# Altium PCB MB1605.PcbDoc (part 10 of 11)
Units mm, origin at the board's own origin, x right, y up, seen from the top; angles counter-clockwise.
Board outline 100 x 79.6 mm, 6 copper layers (Top Layer, Signal Layer 1, Signal Layer 2, Signal Layer 3, Signal Layer 4, Bottom Layer), stack 1.549 mm thick; 644 components, 529 nets, 2853 pads, 1462 vias.
Unrouted connection lines stored in the file: 2.
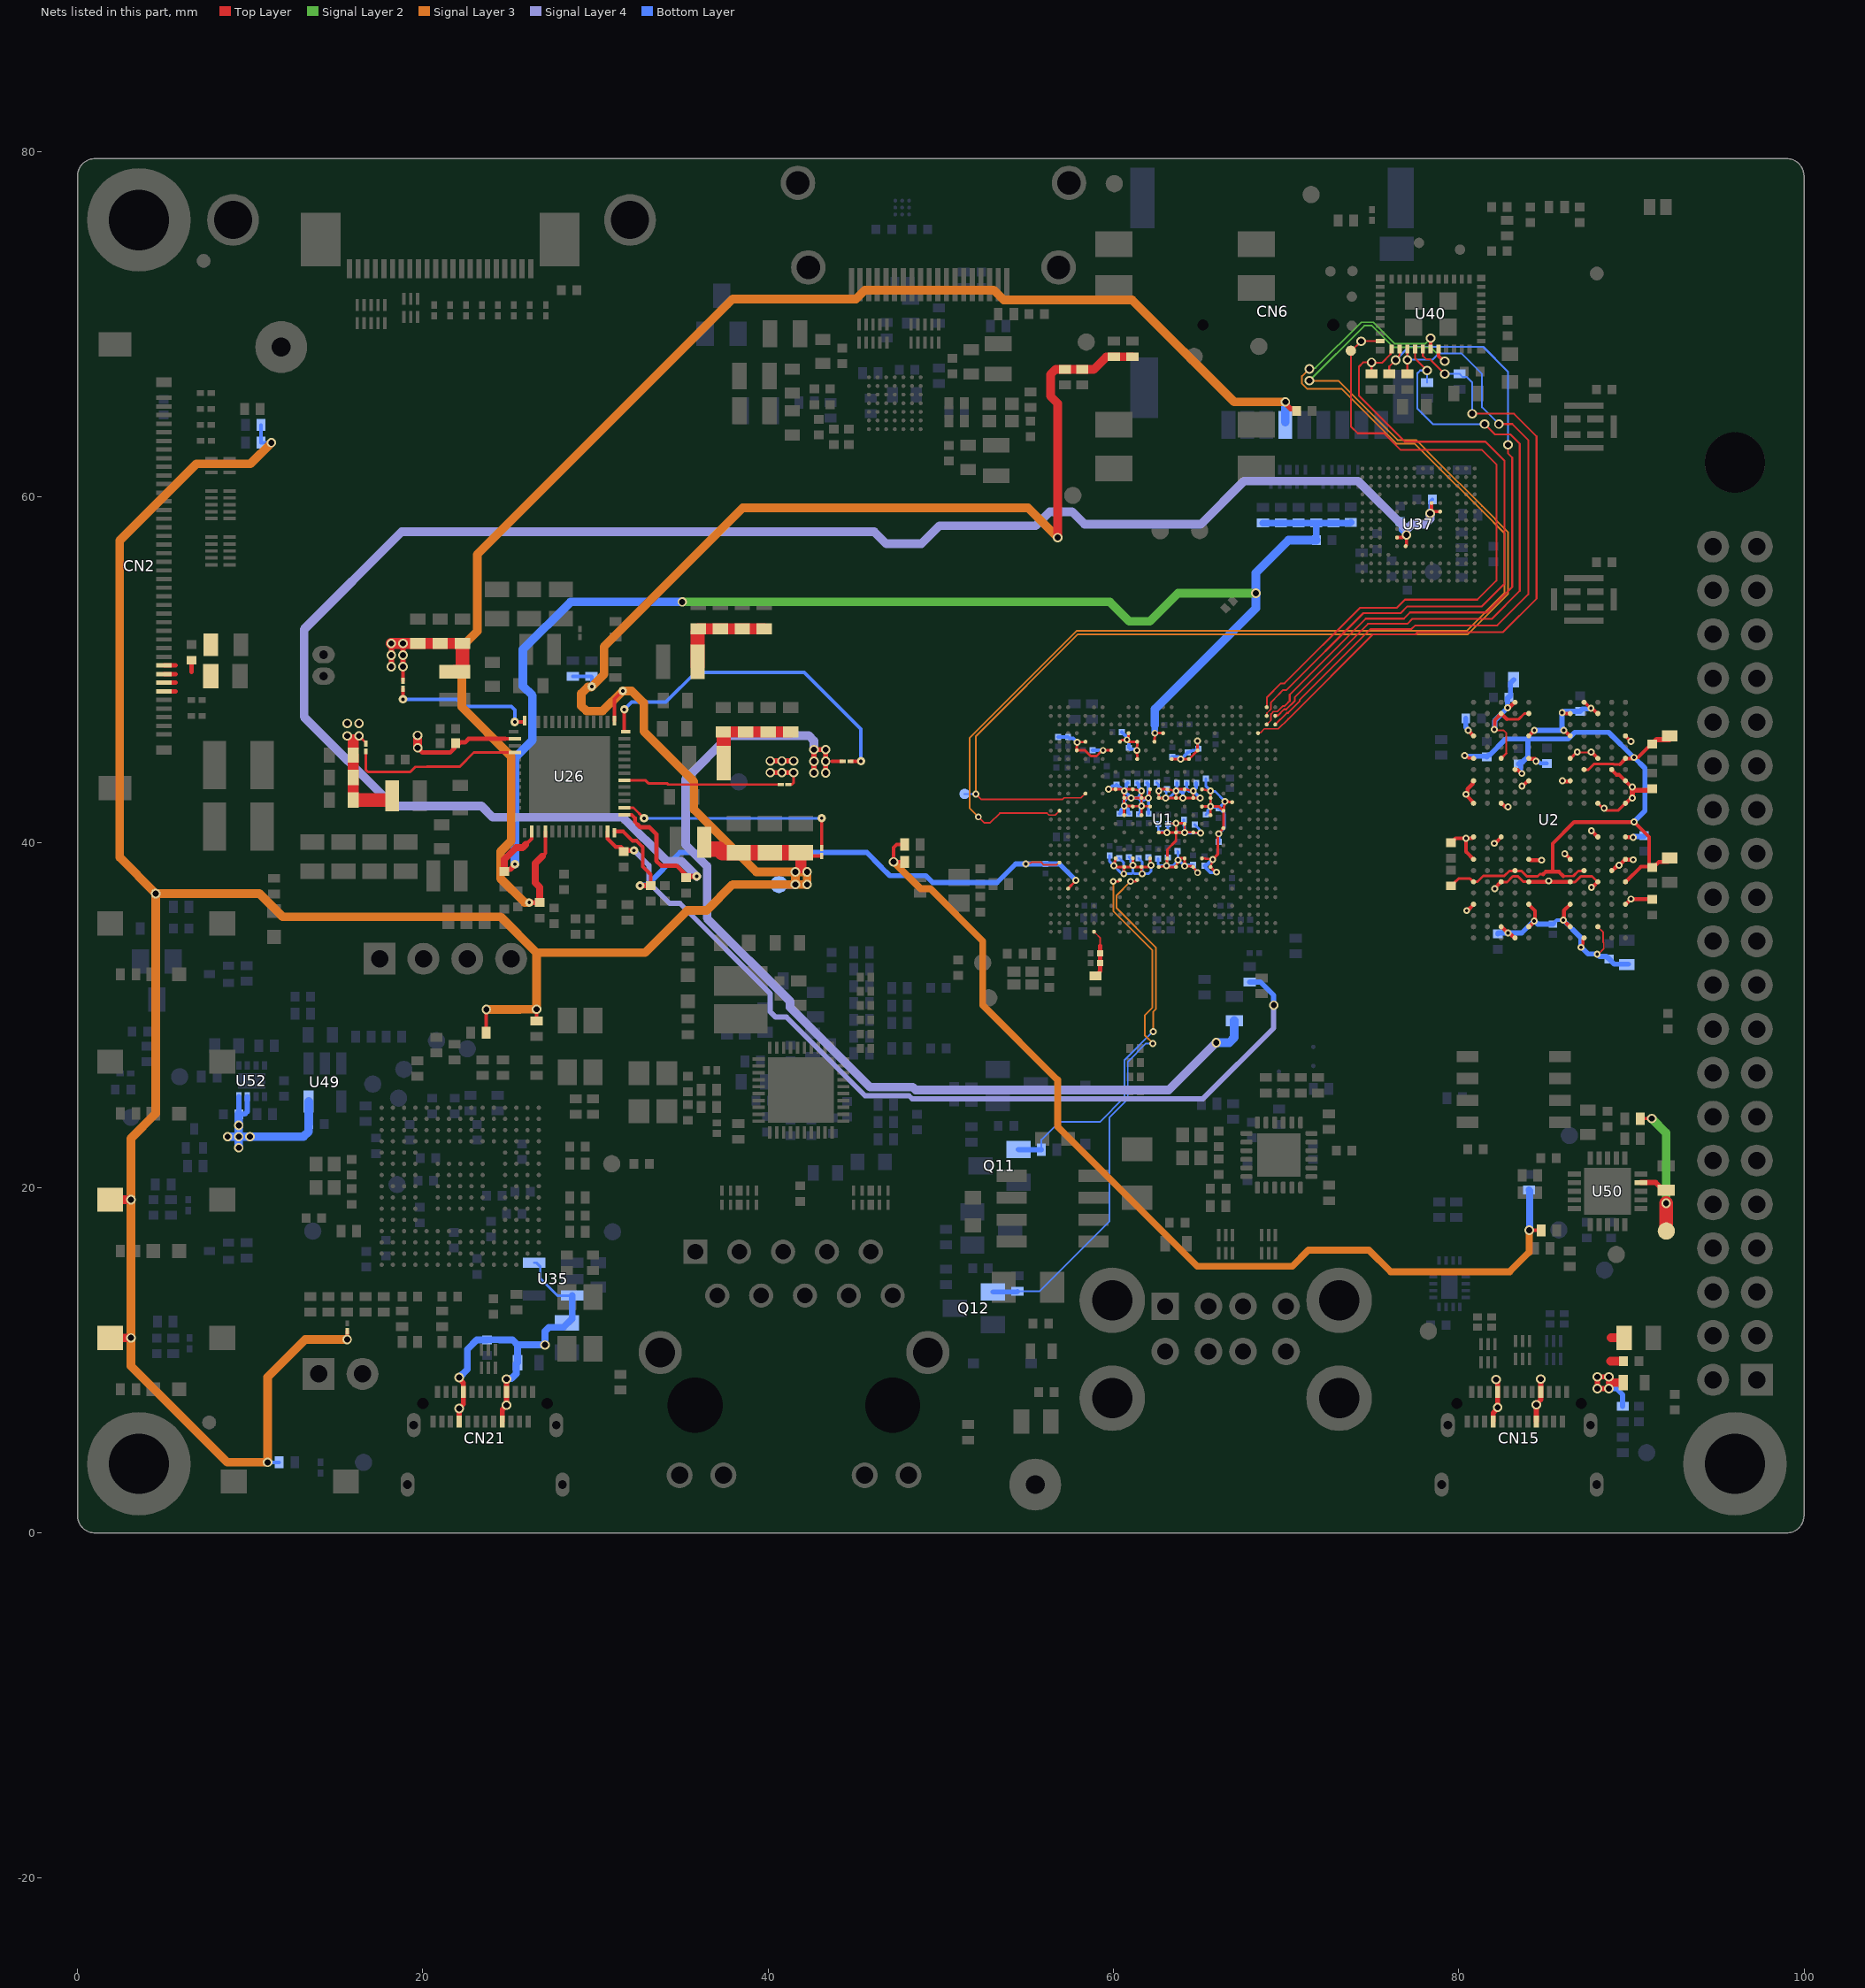
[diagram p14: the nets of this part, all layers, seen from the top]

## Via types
v1: diameter 0.55, hole 0.35, Top Layer to Bottom Layer, 823 vias
v2: diameter 0.4, hole 0.2, Top Layer to Bottom Layer, 235 vias
v3: diameter 0.4, hole 0.2, Top Layer to Bottom Layer, tented both sides, 216 vias
v4: diameter 0.5, hole 0.2, Top Layer to Bottom Layer, 159 vias
v5: diameter 0.25/0.3 (per signal layer), hole 0.1, Top Layer to Signal Layer 1, tented both sides, 29 vias

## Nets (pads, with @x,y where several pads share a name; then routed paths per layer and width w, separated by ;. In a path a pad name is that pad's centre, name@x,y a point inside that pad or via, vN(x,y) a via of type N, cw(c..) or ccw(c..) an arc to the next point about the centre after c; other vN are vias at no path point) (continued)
VBUS_STLK: C110.2 C164.1 C166.2 C172.2 CN21.A4 CN21.A9 CN21.B4 CN21.B9 U35.3 U35.5 U48.1 U49.5 U52.3 U52.4 | length 32.7
  Top Layer w0.3: CN21.B9@22.1,6.46 v1(22.1,7.213) 22.35,7.463 CN21.A4@22.35,8.16 22.35,8.682 22.1,8.932 v1(22.1,9) ; CN21.B4@24.6,6.46 24.6,7.15 v1(24.85,7.4) CN21.A9@24.85,8.16 v1(24.85,8.913)
  Bottom Layer w0.15: U35.5@26.446,15.65 26.579,15.65 26.804,15.425 26.804,14.739 27.793,13.75 U35.3@28.646,13.75
  Bottom Layer w0.3: U52.4@9.336,25.277 C172.2@9.336,24.257 9.686,24.257 9.836,24.407 U52.3@9.836,25.277
  Bottom Layer w0.4: v1(22.1,9) 22.575,9.475 22.575,10.629 23.13,11.184 23.707,11.184 C164.1@23.71,11.187 24.46,11.187 24.461,11.186 25.19,11.186 25.485,10.891 ; v1(24.85,8.913) 24.879,8.942 25.129,8.942 25.41,9.223 25.41,9.79 U48.1@25.485,9.865 25.485,10.891 ; U35.3@28.646,13.75 28.646,12.413 28.146,11.913 27.309,11.913 27.074,11.678 v1(27.074,10.891) 25.485,10.891
  Bottom Layer w0.5: v1(8.691,22.955) v1(9.336,22.955) ; v1(9.336,22.31) v1(9.336,22.955) ; C172.2@9.336,24.257 v1(9.336,23.612) v1(9.336,22.955) ; C166.2@13.39,23.667 U49.5@13.39,24.984 ; C166.2@13.39,23.691 13.385,23.686 13.385,23.248 13.093,22.955 v1(9.336,22.955)
  other v1: 9.981,22.955
VBUSc: C156.2 C159.2 CN15.A4 CN15.A9 CN15.B4 CN15.B9 R219.2 R225.1 R232.1 TP39.1 U43.1 U50.9 | length 20.2
  Top Layer w0.2: R232.1@90.513,24.003 v1(91.188,24.003)
  Top Layer w0.3: CN15.B9@82,6.46 82,6.953 82.25,7.203 v1(82.25,7.27) 82.25,8.732 82.163,8.82 v1(82.163,8.888) ; CN15.B4@84.5,6.461 84.5,6.696 84.499,6.697 84.499,7.472 84.75,7.723 v1(84.75,8.913) ; v1(88.7,8.364) v1(88.025,8.364) v1(88.025,9.039) v1(88.7,9.039) ; U50.9@90.538,20.298 91.408,20.298 91.833,19.873 R225.1@92.013,19.873
  Top Layer w0.5: 88.775,8.702 U43.1@89.525,8.702 ; 88.8,9.952 C156.2@89.55,9.952 ; 88.825,11.302 C159.2@89.575,11.302
  Top Layer w0.8: TP39.1@92.013,17.502 v1(92.013,19.098)
  Signal Layer 2 w0.5: v1(91.188,24.003) 92.013,23.178 v1(92.013,19.098)
  Bottom Layer w0.3: v1(88.7,8.364) 89.138,8.364 89.5,8.002 R219.2@89.5,7.329
  other v1: 84.499,7.422
VCONN_CC1_EN: Q11.1 R41.2 U1.AA11 | length 22.7
  Top Layer w0.15: v3(60.989,37.734) v3(60.989,37.734) 61.264,37.736 61.353,37.825 U1.AA11@61.375,37.825
  Signal Layer 3 w0.1: v3(60.989,37.734) 60.179,36.925 60.179,36.188 62.458,33.909 62.458,30.34 62.301,30.184 v2(62.301,29.041)
  Bottom Layer w0.1: R41.2@55.825,22.2 55.825,22.775 56.858,23.807 59.219,23.807 60.633,25.221 60.633,27.372 v2(62.301,29.041)
  Bottom Layer w0.3: Q11.1@54.5,22.213 54.512,22.2 R41.2@55.825,22.2
VCONN_CC2_EN: Q12.1 R200.2 U1.AA9 | length 31.1
  Top Layer w0.15: v3(59.989,37.734) v3(59.989,37.734) 60.264,37.736 60.353,37.825 U1.AA9@60.375,37.825
  Signal Layer 3 w0.1: v3(59.989,37.734) 59.989,36.015 61.929,34.075 62.258,33.746 62.258,30.423 61.825,29.99 61.825,28.808 v2(62.283,28.35)
  Bottom Layer w0.1: R200.2@54.438,13.988 55.706,13.988 59.774,18.056 59.774,24.08 60.833,25.138 60.833,27.289 61.894,28.35 v2(62.283,28.35)
  Bottom Layer w0.3: Q12.1@53.022,13.963 54.413,13.963 R200.2@54.438,13.988
VDD1_DDR: C2.2 C3.2 C4.1 C5.1 C6.1 C7.1 C8.1 C40.2 U2.F1 U2.F12 U2.G4 U2.G9 U2.T4 U2.T9 U2.U1 U2.U12 U26.44 | length 53
  Top Layer w0.15: C5.1@79.559,37.479 79.584,37.479 C5.1@79.764,37.659 ; C5.1@79.765,37.66 79.765,37.68 79.979,37.894 80.659,37.894 80.859,37.694 80.888,37.723 81.088,37.723 81.415,38.05 82.641,38.05 82.936,38.345 83.277,38.345 83.28,38.348 83.628,38.348 83.945,38.032 84.577,38.032 84.698,38.153 84.893,38.153 ; 86.059,38.044 86.632,38.044 86.925,38.337 87.252,38.337 U2.G4@87.259,38.344 ; U2.T4@87.259,44.215 87.518,44.215 87.837,44.534 88.977,44.534 88.992,44.519 89.33,44.519
  Top Layer w0.2: v2(80.34,45.025) 80.421,45.025 80.56,44.886 80.839,44.886 U2.U12@80.86,44.865
  Top Layer w0.21: 24.775,46 U26.44@25.33,46
  Top Layer w0.22: U2.T9@83.26,44.215 83.275,44.2 83.415,44.2 83.625,43.99 v2(83.659,43.99) ; 84.893,38.153 85.034,38.294 85.44,38.294 ; 86.059,38.044 85.809,38.294 85.44,38.294 ; 89.33,44.519 89.655,44.844 89.659,44.844 90,44.844 90.075,44.919 90.384,44.919 91.159,45.694 C6.1@91.184,45.694 ; U2.F1@89.65,37.683 90.561,38.594 91.179,38.594 91.034,38.739 91.034,40.316 v2(90.16,41.19) ; v2@90.146,41.176 86.685,41.176 85.44,39.931 85.44,38.294 ; C7.1@91.21,38.54 91.355,38.685 C7.1@91.411,38.685 ; C7.1@91.41,38.685 91.588,38.863 92.127,38.863 C3.2@92.183,38.919
  Top Layer w0.25: v1(19.7,46.198) v1@19.702,46.196 ; v1@19.725,45.473 v1(19.702,45.473) 19.975,45.2 21.575,45.2 21.82,45.445 21.82,45.635 21.935,45.75 C40.2@22.005,45.75 ; C40.2@22.01,45.635 22.165,45.79 22.44,45.79 22.65,46 24.775,46
  Top Layer w0.3: C6.1@91.184,45.694 C6.1@91.209,45.694 ; C6.1@91.208,45.694 91.458,45.944 C2.2@92.208,45.944
  Top Layer w0.5: v1(19.702,45.473) v1@19.702,46.196
  Bottom Layer w0.2: v2(80.34,45.025) v2@80.376,44.988 ; C4.1@81.592,44.988 C4.1@81.628,44.952
  Bottom Layer w0.22: C8.1@83.459,44.545 C8.1@83.48,44.545
  Bottom Layer w0.3: v2@80.376,44.988 C4.1@81.592,44.988 ; C4.1@81.628,44.952 81.733,45.057 81.787,45.057 82.72,45.99 84.005,45.99 84.017,45.99 ; C8.1@83.471,44.533 C8.1@83.484,44.545 ; C8.1@83.48,44.545 C8.1@83.484,44.545 ; v2@83.658,43.995 83.589,44.064 83.589,44.44 C8.1@83.484,44.545 ; v2@90.158,41.195 90.783,41.82 90.783,44.295 v2@90.158,44.92 ; v2@90.158,44.895 88.683,46.37 86.722,46.37 86.342,45.99 84.017,45.99 ; C8.1@83.484,44.545 83.589,44.65 83.693,44.65 84.017,44.974 84.017,45.99
  other v2: 90.16,44.915
VDD2_DDR: C10.2 C11.2 C12.1 C13.1 C14.1 C15.1 C16.1 C17.1 C18.1 C19.1 C20.1 C21.1 C41.2 C75.2 C76.2 C77.1 C82.2 C83.2 C200.2 C202.2 L5.2 LNK8.2 R2.2 U1.1C11 U1.1D12 U1.1E11 U1.1F12 U1.1L11 U1.1M12 U1.M22 U1.N21 U1.R21 U2.A4 U2.A9 U2.AA3 U2.AA5 U2.AA8 U2.AA10 U2.AB4 U2.AB9 U2.B3 U2.B5 U2.B8 U2.B10 U2.D1 U2.D5 U2.D8 U2.D12 U2.F3 U2.F5 U2.F8 U2.F10 U2.G2 U2.H1 U2.H5 U2.H8 U2.H12 U2.K1 U2.K3 U2.K10 U2.K12 U2.N1 U2.N3 U2.N10 U2.N12 U2.R1 U2.R5 U2.R8 U2.R12 U2.T2 U2.U3 U2.U5 U2.U8 U2.U10 U2.W1 U2.W5 U2.W8 U2.W12 | length 85.6
  Top Layer w0.09: v2@82.121,46.482 82.614,46.482 82.754,46.341 82.754,45.159 ; U2.U5@86.46,44.865 U2.U5@86.48,44.865 ; v2@86.844,45.229 v2(86.865,45.229) 86.89,45.204 87.64,45.204 v2(87.665,45.229) ; U2.AB4@87.26,48.115 U2.AB4@87.285,48.115 ; v2@87.635,47.765 v2(87.659,47.765) ; v2(88.016,33.516) 88.083,33.516 88.405,33.838 88.405,34.168 88.369,34.204 88.369,34.784 U2.B3@88.059,35.094 ; U2.K1@89.659,40.369 U2.K1@89.684,40.369
  Top Layer w0.1: U2.W8@84.06,46.165 U2.W8@84.06,46.167 ; v2@84.38,46.487 v2(84.38,46.49) ; U2.W1@89.66,46.158 U2.W1@89.66,46.165 ; v2(89.972,45.84) v2@89.972,45.846
  Top Layer w0.15: v1(16.298,46.165) 16.7,45.763 LNK8.2@16.7,45.723 ; U1.1L11@65.125,39.075 v3(65.75,39) U1.1M12@65.625,38.575 v3@65.925,38.25 ; U1.1E11@65.125,42.075 v3(65.625,42.075) ; U1.1C11@65.125,43.075 v3(65.625,42.984) U1.1D12@65.625,42.575 v3(65.625,42.075) ; U1.1F12@65.625,41.575 v3(65.625,42.075) ; U2.F10@82.459,37.694 82.469,37.704 82.803,37.704 83.129,38.03 83.389,38.03 ; U2.U10@82.46,44.865 82.754,45.159 ; 82.785,47.138 83.478,47.138 83.805,47.465 U2.AA8@84.06,47.465 ; 83.39,38.029 83.43,38.029 83.741,37.719 U2.F8@84.059,37.719 ; U2.F5@86.459,37.694 86.734,37.694 87.072,38.032 87.721,38.032 U2.F3@88.034,37.719 ; U2.U5@86.48,44.865 v2@86.844,45.229
  Top Layer w0.16: v3(65.625,42.075) 66.125,42.075 U1.N21@66.375,41.825 ; v3(65.75,39) 66.042,39.292 66.042,40.377 66.1,40.435 v3(66.1,40.5) U1.R21@66.375,40.825 U1.N21@66.375,41.825 ; U1.M22@66.875,42.325 v3(66.458,42.372) U1.N21@66.375,41.825 ; v2(87.076,33.92) 87.076,33.985 87.193,34.102 87.193,34.105 87.196,34.108 87.196,34.363 87.26,34.427 U2.A4@87.26,34.465 ; U2.N3@88.06,42.265 88.35,41.975 v2(88.425,41.975) 88.546,41.854 89.249,41.854 U2.N1@89.66,42.265
  Top Layer w0.2: v2@80.546,46.484 v2(80.546,46.49) ; U2.W12@80.86,46.165 U2.W12@80.86,46.171 ; v2(82.835,47.79) 82.873,47.828 v2@82.946,47.828 ; U2.AB9@83.233,48.115 U2.AB9@83.26,48.115 ; v2(85.99,47.505) 86.03,47.465 U2.AA5@86.46,47.465 ; U2.AB4@87.285,48.115 v2@87.635,47.765 ; v2(87.659,47.765) 87.697,47.727 87.771,47.727 88.033,47.465 U2.AA3@88.06,47.465 ; U2.W1@89.66,46.158 v2@89.972,45.846
  Top Layer w0.22: C13.1@79.559,39.979 79.814,40.235 v2(80.415,40.235) ; v2@80.488,36.045 80.51,36.045 U2.D12@80.859,36.394 ; v2@80.546,46.484 U2.W12@80.86,46.171 ; U2.H12@80.859,39.021 80.421,39.459 80.421,40.229 v2(80.415,40.235) ; U2.K12@80.859,40.294 80.856,40.297 U2.K12@80.842,40.297 ; U2.K12@80.86,40.315 U2.K12@80.842,40.297 ; U2.N12@80.86,42.265 80.86,42.301 80.414,42.747 v2(80.414,42.784) 80.414,42.832 80.504,42.922 80.504,42.924 80.51,42.93 80.51,43.093 80.82,43.403 80.82,43.503 80.86,43.543 U2.R12@80.86,43.565 ; v2@82.059,39.919 82.072,39.919 82.447,40.294 U2.K10@82.459,40.294 ; v2@82.086,37.344 82.436,37.694 U2.F10@82.459,37.694 ; v2@82.089,46.574 82.089,47.074 82.459,47.444 82.479,47.444 82.785,47.138 ; U2.B10@82.459,35.094 82.462,35.097 82.493,35.097 82.845,34.744 v2(82.86,34.744) ; U2.N10@82.459,42.244 82.491,42.244 82.497,42.25 82.672,42.074 82.826,42.074 v2@82.86,42.04 ; v2@82.859,34.719 82.893,34.685 82.997,34.685 83.237,34.444 U2.A9@83.259,34.444 ; v2@82.946,47.828 U2.AB9@83.233,48.115 ; v2(83.66,43.253) 83.704,43.253 84.016,43.565 U2.R8@84.06,43.565 ; U2.B8@84.059,35.094 v2@84.384,35.419 ; U2.D8@84.059,36.394 84.419,36.034 v2@84.419,35.503 ; U2.F8@84.059,37.719 84.072,37.707 85.122,37.706 85.134,37.719 85.147,37.706 86.447,37.706 U2.F5@86.459,37.694 ; U2.H8@84.059,39.015 84.081,39.015 84.131,38.965 v2(84.809,38.965) ; U2.U8@84.059,44.844 84.074,44.829 84.426,44.829 84.46,44.794 v2@84.509,44.794 ; U2.W8@84.06,46.167 v2@84.38,46.487 ; v2(86.01,43.565) 86.042,43.532 U2.R5@86.422,43.532 ; v2(86.085,46.49) 86.11,46.49 86.435,46.165 U2.W5@86.46,46.165 ; v2(86.145,39.34) U2.H5@86.46,39.025 ; U2.B5@86.459,35.094 86.059,35.494 86.089,35.524 86.089,36.044 U2.D5@86.46,36.415 ; v2@87.679,45.243 88.032,44.891 88.032,44.883 U2.U3@88.059,44.856 ; v2(87.685,37.39) 87.733,37.39 87.817,37.474 88.037,37.694 U2.F3@88.059,37.694 ; v2(87.685,40.665) 87.697,40.665 88.046,40.316 U2.K3@88.059,40.316 ; U2.T2@88.832,44.199 88.854,44.199 89.134,43.919 89.284,43.919 89.95,43.253 90.025,43.253 v2@90.059,43.219 ; U2.G2@88.859,38.344 88.881,38.344 v2@89.171,38.635 ; v2(89.285,38.665) 89.298,38.665 89.628,38.995 89.658,38.995 89.659,38.994 v2@90.109,38.994 ; U2.D1@89.659,36.394 89.984,36.719 C15.1@91.159,36.719 ; U2.K1@89.659,40.307 89.659,40.294 v2@90.109,40.294 ; U2.N1@89.659,42.244 89.95,42.535 90.025,42.535 v2@90.059,42.569 ; v2(80.415,40.235) 80.78,40.235 U2.K12@80.842,40.297
  Top Layer w0.3: v2@90.059,42.569 v2@90.059,43.219 ; 90.259,43.014 91.079,43.014 C14.1@91.184,43.119
  Top Layer w0.64: C202.2@15.975,42.45 C41.2@15.975,43.75 C200.2@15.975,45.05 ; 15.975,45.495 15.975,45.925
  Top Layer w0.8: C202.2@16.2,42.45 L5.2@17.975,42.45
  Bottom Layer w0.15: C82.2@65.352,41.603 65.452,41.703 65.452,41.862 65.625,42.035 v3(65.625,42.075) ; C83.2@65.363,43.698 65.363,43.246 v3(65.625,42.984) ; C75.2@66.083,41.967 66.023,42.027 65.673,42.027 v3(65.625,42.075) ; v3(66.458,42.372) 65.886,42.944 65.665,42.944 v3(65.625,42.984) ; v3(65.625,42.075) v3(65.625,42.984)
  Bottom Layer w0.16: v3(66.1,40.5) 66.44,40.84 66.44,41.65 66.218,41.872 66.178,41.872 C75.2@66.083,41.967 66.458,42.342 v3(66.458,42.372)
  Bottom Layer w0.2: C76.2@65.274,38.648 65.349,38.573 65.349,38.508 65.607,38.25 v3@65.925,38.25 ; C76.2@65.291,38.665 65.349,38.723 65.438,38.723 65.715,39 v3(65.75,39)
  Bottom Layer w0.22: C77.1@66.1,40.025 v3(66.1,40.5) ; v2@84.508,44.795 84.729,44.574 85.104,44.574 C21.1@85.108,44.57 ; R2.2@85.408,35.22 85.458,35.22 85.548,35.31 85.548,35.36 85.683,35.495 v2@86.058,35.495
  Bottom Layer w0.3: C12.1@80.409,47.185 80.409,46.676 80.546,46.539 v2(80.546,46.49) ; v2(82.06,46.54) 82.079,46.559 82.079,47.034 v2(82.835,47.79) ; C19.1@82.259,34.71 82.299,34.749 83.652,34.749 84.323,35.42 84.377,35.42 84.401,35.445 84.576,35.27 R2.2@85.459,35.27 ; v2@82.833,47.795 82.833,48.37 C16.1@82.909,48.446 ; C16.1@82.909,48.395 82.995,48.48 82.995,49.23 C10.2@83.184,49.42 ; v2(84.38,46.49) v2(86.085,46.49) 86.085,46.539 85.99,46.634 v2(85.99,47.505) 86.039,47.505 86.129,47.595 C17.1@87.034,47.595 87.169,47.731 87.625,47.731 v2(87.659,47.765) ; v2@86.059,35.495 87.076,34.478 v2(87.076,33.92) 87.103,33.92 87.488,33.536 87.997,33.536 v2(88.016,33.516) 88.087,33.46 88.161,33.402 88.552,33.402 88.579,33.35 C18.1@88.704,33.249 ; C18.1@88.603,33.35 C18.1@88.704,33.249 ; C18.1@88.709,33.245 C18.1@88.704,33.249 ; C11.2@89.833,32.945 89.008,32.945 C18.1@88.704,33.249 ; v2@90.108,40.295 90.142,40.33 90.717,40.33 C20.1@90.758,40.37
  other v1: 15.623,46.165 15.623,46.89 16.298,46.89
  other v2: 84.375,35.44 86.06,35.49 80.46,36.045 89.985,36.715 82.085,37.315 85.21,37.765 90.11,38.99 82.06,39.94 90.11,40.29 82.86,42.05 90.06,42.565 90.06,43.215 84.479,44.694
  other v3: 65.975,38.275
VDD2_DDR_FB: LNK8.1 U26.46 | length 10.2
  Top Layer w0.15: LNK8.1@16.7,45.273 16.7,44.19 16.817,44.073 19.267,44.073 19.567,44.373 20.237,44.373 20.239,44.375 22.127,44.375 22.952,45.2 U26.46@25.33,45.2
VDD3V3_USB: C61.2 R286.1 U26.13 | length 51.8
  Top Layer w0.21: U26.13@30.7,40.63 30.7,40.2 31.163,39.737 31.418,39.737 31.42,39.735 31.49,39.735 31.625,39.6 C61.2@31.625,39.53
  Top Layer w0.3: C61.2@31.625,39.53 v4(32.235,39.53)
  Signal Layer 4 w0.3: v4(32.235,39.53) 33.09,38.675 33.09,37.669 34.292,36.467 34.893,36.467 40.125,31.235 40.125,30.183 40.433,29.875 41.06,29.875 45.61,25.325 48.162,25.325 48.337,25.15 65.19,25.15 69.284,29.244 v1(69.284,30.569)
  Bottom Layer w0.3: R286.1@67.89,31.915 67.898,31.908 68.514,31.908 69.284,31.138 v1(69.284,30.569)
VDD_EMMC: C9.2 C117.2 C190.1 U26.16 U37.E6 U37.F5 U37.J10 U37.K9 | length 114.2
  Top Layer w0.2: U37.E6@76.425,57.655 76.73,57.655 76.88,57.805 v1(76.975,57.805) ; U37.F5@76.925,57.155 76.925,57.163 76.975,57.213 v1@76.975,57.655 ; v1(78.35,59.055) v1@78.425,59.13 ; U37.J10@78.425,59.655 78.425,59.225 78.417,59.217 78.417,59.138 v1@78.425,59.13 ; U37.K9@78.925,59.155 78.545,59.155 78.512,59.122 78.433,59.122 v1@78.425,59.13
  Top Layer w0.21: U26.16@31.67,41.6 32.1,41.6 32.288,41.412 32.288,41.187 32.434,41.041
  Top Layer w0.25: 32.432,41.038 32.598,40.872 33.128,40.872 33.525,40.475 33.525,38.925 33.8,38.65 34.695,38.65 35.25,38.095 C190.1@35.25,38.025
  Top Layer w0.3: C190.1@35.25,38.025 v4(35.86,38.025)
  Signal Layer 4 w0.5: v4(35.86,38.025) 34.965,38.92 34.111,38.92 31.581,41.45 24.048,41.45 23.398,42.1 18.289,42.1 13.124,47.265 13.124,52.342 18.772,57.99 46.146,57.99 46.841,57.296 48.877,57.296 49.915,58.333 55.502,58.333 56.307,59.139 57.609,59.139 58.324,58.425 65.064,58.425 67.565,60.926 74.175,60.926 76.985,58.117 77.293,58.425 78.032,58.425 78.34,58.733 78.34,59.045 v1(78.35,59.055)
  Bottom Layer w0.2: C9.2@76.615,58.58 76.615,58.074 76.884,57.805 v1(76.975,57.805) ; v1(78.35,59.055) 78.35,59.739 C117.2@78.475,59.864
VDD_SDCARD: C215.1 C218.2 CN6.4 U26.4 | length 85.8
  Top Layer w0.21: 26.925,39.2 27.1,39.375 U26.4@27.1,40.63
  Top Layer w0.3: v4(26.165,36.51) C215.1@26.775,36.51 ; v1(69.96,65.511) 70.008,65.463 70.008,65.373 70.261,65.12 70.505,65.12 70.61,65.015 C218.2@70.61,64.99
  Top Layer w0.4: C215.1@26.775,36.51 26.775,37.393 26.51,37.658 26.51,38.785 26.925,39.2
  Signal Layer 3 w0.5: v4(26.165,36.51) 25.89,36.51 24.5,37.9 24.5,39.467 25.115,40.083 25.115,44.981 22.253,47.843 22.253,51.327 23.158,52.232 23.158,56.674 37.95,71.466 45.091,71.466 45.605,71.98 53.072,71.98 53.639,71.413 61.083,71.413 66.984,65.511 v1(69.96,65.511)
  Bottom Layer w0.5: CN6.4@69.96,64.35 v1(69.96,65.511)
VDDA1V8_AON: C189.2 C234.2 U1.AB3 U1.W2 U26.14 | length 35.4
  Top Layer w0.09: 56.026,38.692 56.705,38.692 56.837,38.825 U1.W2@56.875,38.825 ; v3@57.825,37.775 v3(57.825,37.8)
  Top Layer w0.1: v2(54.932,38.744) 54.99,38.801 55.205,38.801 55.267,38.863 55.805,38.863 55.975,38.692 56.026,38.692
  Top Layer w0.15: U1.AB3@57.375,37.325 v3@57.825,37.775
  Top Layer w0.21: U26.14@31.1,40.63 31.61,40.63 32.148,40.092 32.387,40.092 32.745,39.734 32.745,38.602 33.2,38.147 C189.2@33.2,37.49
  Top Layer w0.3: v4(32.59,37.49) C189.2@33.2,37.49
  Bottom Layer w0.3: v4(32.59,37.49) 32.628,37.528 33.005,37.528 34.887,39.41 45.714,39.41 46.542,38.582 46.542,38.57 47.042,38.07 49.132,38.07 49.531,37.67 53.261,37.67 54.334,38.744 v2(54.932,38.744) 54.936,38.748 C234.2@56.064,38.748 56.877,38.748 v3(57.825,37.8)
VDDCORE: C22.2 C23.2 C24.2 C44.1 C45.2 C46.2 C47.1 C48.2 C49.2 C50.2 C51.2 C183.2 C192.2 C197.2 C201.2 L2.2 LNK2.2 R11.1 U1.1C1 U1.1C3 U1.1C5 U1.1D2 U1.1D4 U1.1E3 U1.1E5 U1.1F2 U1.1F4 U1.E5 U1.F4 U1.F8 | length 86.8
  Top Layer w0.15: U1.E5@58.375,45.825 v3(57.9,45.8) U1.F4@57.875,45.325 58.365,45.325 58.685,45.005 59.019,45.005 59.339,45.325 v3(59.4,45.325) U1.F8@59.875,45.325 ; v3(59.725,43.075) U1.1C1@60.125,43.075 60.534,43.075 v3(60.625,42.983) ; U1.1F2@60.625,41.575 v3(60.625,42.1) ; U1.1F4@61.625,41.575 v3(61.625,42.1) ; U1.1E5@62.125,42.075 v3(61.625,42.1) ; U1.1C5@62.125,43.075 v3(62.017,42.572) U1.1D4@61.625,42.575 ; v3(60.625,42.1) U1.1D2@60.625,42.575 ; v3(60.625,42.1) 61.1,42.1 U1.1E3@61.125,42.075 v3(61.625,42.1) ; U1.1D2@60.625,42.575 v3(60.625,42.983) ; U1.1D2@60.625,42.575 v3(61.017,42.572) 61.622,42.572 U1.1D4@61.625,42.575 ; v3(60.625,42.983) 60.717,43.075 U1.1C3@61.125,43.075 v3(61.625,42.983) U1.1D4@61.625,42.575 ; v3(61.625,42.1) U1.1D4@61.625,42.575
  Top Layer w0.2: C22.2@39.775,52.375 C22.2@39.823,52.423 ; 43.7,44.7 LNK2.2@44.316,44.7
  Top Layer w0.3: v1(42.656,44.024) v1(42.656,44.699) v1(42.656,45.374) v1(43.331,45.374) v1(43.331,44.699) v1(43.331,44.024)
  Top Layer w0.64: C183.2@35.95,52.375 C24.2@37.225,52.375 C23.2@38.5,52.375 C22.2@39.775,52.375
  Top Layer w0.8: L2.2@35.915,50.2 L2.2@35.915,50.45 C183.2@35.915,52.173
  Signal Layer 4 w0.5: v1(42.656,45.374) 42.656,45.88 42.363,46.173 37.744,46.173 35.227,43.656 35.227,39.858 36.46,38.625 36.46,35.607 41.275,30.792 41.275,30.441 45.891,25.825 48.37,25.825 48.545,25.65 63.206,25.65 v1@65.947,28.391
  Bottom Layer w0.2: C192.2@56.8,46.1 C201.2@57.375,46.1 57.45,46.025 57.675,46.025 v3(57.9,45.8) ; C197.2@58.788,45.342 59.383,45.342 v3(59.4,45.325) ; v3(59.725,43.075) 59.747,43.075 59.942,43.27 60.098,43.27 C45.2@60.173,43.345 v3(60.625,42.983) ; C44.1@60.351,41.659 60.355,41.659 60.426,41.73 60.426,41.883 60.625,42.082 v3(60.625,42.1) ; C51.2@60.814,43.438 60.739,43.363 60.739,43.151 60.625,43.038 v3(60.625,42.983) ; C46.2@60.915,41.655 60.84,41.73 60.84,41.94 60.719,42.062 60.663,42.062 v3(60.625,42.1) ; C49.2@61.377,43.437 61.452,43.362 61.452,43.201 61.625,43.028 v3(61.625,42.983) 61.455,42.572 ; C47.1@61.476,41.631 61.551,41.706 61.551,41.972 61.625,42.046 v3(61.625,42.1) 61.623,42.102 61.623,42.405 ; C50.2@61.941,43.438 62.017,43.362 v3(62.017,42.572) ; C48.2@62.038,41.657 62.038,42.551 v3(62.017,42.572) ; v3(60.625,42.1) 60.625,42.423 60.774,42.572 v3(61.017,42.572) ; v3(60.625,42.983) 61.017,42.591 v3(61.017,42.572) ; v3(61.017,42.572) 61.455,42.572 ; 61.455,42.572 61.623,42.405 ; 61.623,42.405 v3(62.017,42.572)
  Bottom Layer w0.5: v1@65.97,28.4 66.707,28.4 67,28.693 R11.1@67,29.675
  other v1: 65.956,28.4
VDDCORE_FB: LNK2.1 U26.28 | length 19.7
  Top Layer w0.2: U26.28@31.67,46.4 v4(31.67,47.7) ; LNK2.1@44.766,44.7 v4(45.376,44.7)
  Bottom Layer w0.2: v4(31.67,47.7) 32.097,48.127 34.077,48.127 35.8,49.85 42.087,49.85 45.376,46.561 v4(45.376,44.7)
VDDCPU: C26.2 C27.2 C28.2 C62.1 C63.2 C64.2 C65.1 C66.2 C67.2 C68.2 C69.2 L3.2 LNK4.1 U1.1C7 U1.1C9 U1.1D6 U1.1D8 U1.1D10 U1.F18 U1.G15 U1.G17 | length 26.3
  Top Layer w0.15: U1.G15@63.375,44.825 v3(63.9,44.825) U1.G17@64.375,44.825 U1.F18@64.875,45.325 v3(64.875,45.875) ; v3(65.017,42.572) U1.1D10@64.625,42.575 ; U1.1D8@63.625,42.575 63.02,42.575 v3(63.017,42.572) U1.1D6@62.625,42.575 v3(62.625,42.983) 62.716,43.075 U1.1C7@63.125,43.075 v3(63.625,42.983) ; U1.1D8@63.625,42.575 v3(63.625,42.983) ; U1.1D8@63.625,42.575 v3(64.017,42.572) 64.622,42.572 U1.1D10@64.625,42.575 ; v3(63.625,42.983) 63.716,43.075 U1.1C9@64.125,43.075 v3(64.625,42.983) U1.1D10@64.625,42.575
  Top Layer w0.2: LNK4.1@18.85,49.35 v1(18.85,50.173)
  Top Layer w0.3: v1(18.175,50.173) v1(18.175,50.848) v1(18.175,51.523) v1(18.85,51.523) v1(18.85,50.848) v1(18.85,50.173)
  Top Layer w0.64: v1(18.175,51.523) v1(18.175,51.523) C27.2@19.7,51.525 C28.2@21,51.525 C26.2@22.3,51.525
  Top Layer w0.8: L3.2@21.85,49.875 22.3,49.875 22.3,51.173
  Bottom Layer w0.15: C63.2@62.506,43.455 62.606,43.355 62.606,43.269 62.608,43.267 62.608,43.001 v3(62.625,42.983) 62.625,42.684 62.737,42.572 v3(63.017,42.572) v3@63.062,42.617 ; C62.1@63.106,43.078 63.062,43.034 v3@63.062,42.617 ; v3(63.625,42.983) 63.261,42.62 63.065,42.62 v3@63.062,42.617 ; v3(64.875,45.875) 64.895,45.855 C66.2@64.895,45.441
  Bottom Layer w0.2: C67.2@63.4,44.95 63.775,44.95 v3(63.9,44.825) 63.933,44.825 64.23,45.122 64.23,45.127 64.3,45.197 C69.2@64.305,45.197 ; C65.1@63.675,43.434 63.675,43.033 v3(63.625,42.983) 64.017,42.903 ; v3(64.017,42.572) 64.017,42.903 ; C68.2@64.239,43.447 64.239,43.125 ; C69.2@64.305,45.202 64.579,45.324 64.778,45.324 C66.2@64.886,45.432 ; v3@64.625,42.964 v3(64.625,42.983) ; C64.2@64.8,43.446 64.8,43.158 v3(64.625,42.983) ; C66.2@64.853,45.445 C66.2@64.886,45.432 ; C66.2@64.895,45.441 C66.2@64.886,45.432 ; C66.2@64.915,45.421 C66.2@64.886,45.432 ; v3(65.017,42.572) v3(64.625,42.983) ; 64.017,42.903 64.239,43.125 ; 64.239,43.125 64.381,42.983 v3(64.625,42.983)
VDDCPU_FB: LNK4.2 U26.42 | length 8.6
  Top Layer w0.2: v4(18.85,48.29) LNK4.2@18.85,48.9 ; v4(25.325,46.975) U26.42@25.895,46.975
  Bottom Layer w0.2: v4(18.85,48.29) 21.979,48.29 22.394,47.875 25.123,47.875 25.325,47.673 v4(25.325,46.975)
VDDGPU: C34.2 C35.2 C36.2 C37.2 C52.2 C53.2 C54.2 C55.2 C57.2 C58.2 C59.2 C60.2 L4.2 LNK7.2 U1.1G7 U1.1G9 U1.1H6 U1.1H8 U1.1H10 U1.1L7 U1.1L9 U1.1M6 U1.1M8 U1.1M10 | length 28.4
  Top Layer w0.1: U1.1H6@62.625,40.575 U1.1H6@62.625,40.61
  Top Layer w0.125: U1.1G9@64.125,41.075 v3(64.125,40.575) U1.1H10@64.625,40.575
  Top Layer w0.15: LNK7.2@41.175,43.35 41.182,43.358 41.385,43.358 41.473,43.445 v1(41.473,44.038) ; U1.1M6@62.625,38.575 v3(63.075,38.65) ; U1.1H6@62.625,40.575 v3(63.1,40.575) U1.1H8@63.625,40.575 ; U1.1G7@63.125,41.075 v3(63.625,41.1) ; v3(64.125,40.575) U1.1H8@63.625,40.575 ; U1.1G9@64.125,41.075 64.1,41.1 v3(63.625,41.1) ; v3(64.876,38.245) U1.1M10@64.625,38.575 64.571,38.629 v3(64.125,38.629) U1.1L9@64.125,39.075 63.851,39.075 v3(63.747,38.971) U1.1M8@63.625,38.575 63.15,38.575 v3(63.075,38.65) ; v3(63.075,38.65) U1.1L7@63.125,39.075 63.125,39.59 63.625,40.09 U1.1H8@63.625,40.575 ; U1.1H8@63.625,40.575 v3(63.625,41.1)
  Top Layer w0.16: U1.1H10@64.625,40.575 v3(65.05,40.55)
  Top Layer w0.2: C35.2@41.55,46.393 C35.2@41.598,46.345
  Top Layer w0.3: v1(40.123,44.038) v1(40.798,44.038) v1(41.473,44.038) ; v1(40.123,44.713) v1(40.798,44.713) v1(41.473,44.713)
  Top Layer w0.64: C37.2@37.4,46.4 C36.2@38.7,46.4 C34.2@40,46.4 C35.2@41.3,46.4
  Top Layer w0.8: L4.2@37.425,44.6 37.425,46.073
  Bottom Layer w0.15: C57.2@62.592,39.053 62.592,38.738 62.68,38.65 v3(63.075,38.65) ; C55.2@62.6,41.05 62.6,40.711 62.688,40.623 63.052,40.623 v3(63.1,40.575) 63.162,40.637 C52.2@63.162,41.057 63.184,41.079 63.603,41.079 v3(63.625,41.1) 63.625,40.719 63.769,40.575 v3(64.125,40.575) ; C60.2@63.154,39.122 63.092,39.06 63.092,38.667 v3(63.075,38.65) ; C59.2@63.714,39.486 63.747,39.453 v3(63.747,38.971) ; C53.2@64.083,41.306 64.083,40.962 64.125,40.919 v3(64.125,40.575) ; C54.2@64.706,41.029 65.002,40.733 65.002,40.598 v3(65.05,40.55) 64.15,40.55 v3(64.125,40.575) ; v3(64.876,38.245) 64.876,38.289 64.707,38.458 64.707,38.597 C58.2@64.607,38.697 64.193,38.697 v3(64.125,38.629) 63.783,38.971 v3(63.747,38.971) ; v3(63.075,38.65) 63.426,38.65 v3(63.747,38.971)
VDDGPU_FB: LNK7.1 U26.21 | length 9.3
  Top Layer w0.15: U26.21@31.55,43.6 32.883,43.6 33.06,43.423 34.14,43.423 34.213,43.35 LNK7.1@40.725,43.35
VDDIO: B4.1 B5.1 C70.1 C71.2 C72.2 C73.1 C74.2 C185.2 C186.2 C187.2 C196.2 C205.2 L6.2 LNK11.2 LNK13.1 R27.2 R31.2 R32.2 R33.2 R44.2 R67.2 R107.2 R122.2 R123.2 R124.2 R125.2 R223.2 R245.2 R246.2 R260.2 R261.2 TP2.1 TP4.1 U1.1L1 U1.1L3 U1.1L5 U1.1M2 U1.1M4 U1.D10 U1.E9 U1.E11 U1.G11 U26.29 | length 294.2
  Top Layer w0.15: U1.1L1@60.125,39.075 v3(60.025,38.65) 60.1,38.575 U1.1M2@60.625,38.575 ; U1.E9@60.375,45.825 60.397,45.825 60.488,45.916 60.756,45.916 v3(60.78,45.94) 60.895,45.825 U1.E11@61.375,45.825 v3(61.35,45.325) U1.G11@61.375,44.825 ; v3(60.6,38.175) U1.1M2@60.625,38.575 ; v3@60.866,46.094 60.866,46.316 U1.D10@60.875,46.325 ; U1.1L3@61.125,39.075 v3(61.125,38.675) ; v3(61.663,38.175) 61.625,38.212 U1.1M4@61.625,38.575 ; U1.1L5@62.125,39.075 62.125,38.793 62.175,38.743 v3(62.175,38.675) 62.075,38.575 U1.1M4@61.625,38.575 ; U1.1M2@60.625,38.575 61.025,38.575 v3(61.125,38.675) ; v3(61.125,38.675) 61.225,38.575 U1.1M4@61.625,38.575
  Top Layer w0.2: v1(15.615,11.207) LNK13.1@15.615,11.687 ; R107.2@23.675,28.982 23.675,30.322 v1(23.677,30.325) ; R125.2@26.59,29.657 v1(26.59,30.332) ; U26.29@31.1,47.045 31.1,48.298 v4(31.575,48.773) ; C186.2@41.9,39.4 42.085,39.215 LNK11.2@43.1,39.215 ; v1(47.267,38.87) 47.267,39.699 47.441,39.873 R245.2@47.905,39.873 ; v1@47.269,38.872 R27.2@47.905,38.872 ; v1(84.08,17.535) R223.2@84.755,17.535
  Top Layer w0.5: B5.1@1.886,11.3 v1(3.095,11.3) ; B4.1@1.886,19.3 v1(3.095,19.3) ; v1(56.775,57.65) 56.775,65.427 56.359,65.843 56.359,67.102 56.652,67.395 57.195,67.395 R44.2@57.2,67.4 R122.2@58.2,67.4 58.201,67.401 58.864,67.401 59.583,68.12 60.02,68.12 R124.2@60.025,68.125 R123.2@61.1,68.125
  Top Layer w0.64: 41.9,38.525 C186.2@41.9,38.955
  Top Layer w0.9: L6.2@36.35,39.6 37.15,39.6 37.35,39.4 C187.2@38.3,39.4 C185.2@40.1,39.4 C186.2@41.9,39.4
  Signal Layer 3 w0.4: v1(47.267,38.87) 48.827,37.31 49.399,37.31 52.431,34.278 52.431,30.573 56.764,26.24 56.764,23.546 64.86,15.45 70.36,15.45 71.294,16.384 74.797,16.384 76.051,15.13 82.951,15.13 84.08,16.259 v1(84.08,17.535)
  Signal Layer 3 w0.5: v1(11.231,63.15) 10.006,61.925 6.875,61.925 2.442,57.492 2.442,39.126 v1(4.532,37.035) ; v1(15.615,11.207) 13.193,11.207 11.011,9.025 v1(11.011,4.09) 8.667,4.09 3.095,9.662 v1(3.095,11.3) v1(3.095,19.3) 3.095,22.849 4.532,24.286 v1(4.532,37.035) ; v1(23.677,30.325) 23.701,30.325 25.627,30.325 25.634,30.332 v1(26.59,30.332) 26.59,33.61 ; v1(56.775,57.65) 55.053,59.372 38.525,59.372 30.5,51.347 30.5,49.743 v4(29.784,49.027) 29.757,49 29.551,49 29.175,48.624 29.175,47.902 29.473,47.603 30.405,47.603 v4(31.575,48.773) 32.102,48.773 32.8,48.075 32.8,46.425 35.7,43.525 35.7,41.9 39.315,38.285 v1(41.577,38.285) ; v1(4.532,37.035) 10.536,37.035 11.883,35.688 24.512,35.688 26.59,33.61 ; 26.59,33.61 32.876,33.61 35.33,36.064 36.454,36.064 37.95,37.56 v1(41.577,37.56) ; v1(41.577,37.56) v1(41.577,38.285) ; v1(41.577,37.56) v1(42.252,37.56) v1(42.252,38.285) v1(41.577,38.285)
  Bottom Layer w0.15: C70.1@59.78,39.235 59.78,38.895 v3(60.025,38.65) 60.452,38.223 60.552,38.223 v3(60.6,38.175) ; C71.2@60.34,39.085 60.6,38.825 v3(60.6,38.175) ; C72.2@60.905,39.148 61.005,39.048 61.005,38.863 61.125,38.743 v3(61.125,38.675) 61.125,38.285 ; C73.1@61.467,39.074 61.663,38.878 v3(61.663,38.175) ; C74.2@62.03,39.133 62.127,39.036 62.127,38.723 v3(62.175,38.675) 62.175,38.323 62.027,38.175 61.235,38.175 61.125,38.285 ; v3(60.6,38.175) 61.037,38.175 61.125,38.263 61.125,38.285
  Bottom Layer w0.2: R32.2@10.625,64.175 R31.2@10.625,63.15 v1(11.231,63.15) ; v1(11.011,4.09) R33.2@11.686,4.09 ; R260.2@28.689,49.621 R261.2@29.763,49.621 29.784,49.6 v4(29.784,49.027) ; C205.2@60.485,46.38 60.742,46.123 60.742,45.978 v3(60.78,45.94) 60.9,45.82 C196.2@60.9,45.475 60.975,45.4 61.221,45.4 61.296,45.325 v3(61.35,45.325)
  Bottom Layer w0.4: R67.2@4.532,35.008 v1(4.532,37.035) ; R246.2@84.074,19.858 84.111,19.82 84.111,17.607 84.08,17.576 v1(84.08,17.535)
  Bottom Layer w0.5: TP2.1@2.136,19.3 v1(3.095,19.3) ; TP4.1@40.618,37.56 v1(41.577,37.56)
VDDIO_FB: LNK11.1 U26.17 | length 13.4
  Top Layer w0.15: U26.17@31.67,42 32.2,42 32.803,41.397 v4(32.815,41.397)
  Top Layer w0.2: LNK11.1@43.1,39.665 v4(43.1,41.4)
  Bottom Layer w0.15: v4(32.815,41.397) 43.097,41.397 v4(43.1,41.4)
VDDIO_SDCARD: C89.2 C195.2 C217.1 R34.2 R35.2 R36.2 R37.2 R38.2 R39.2 U1.D14 U1.E13 U26.2 | length 84.8
  Top Layer w0.15: U1.E13@62.375,45.825 v3(62.4,46.325) U1.D14@62.875,46.325
  Top Layer w0.21: 25.959,39.873 26.3,40.214 U26.2@26.3,40.63
  Top Layer w0.3: C217.1@24.725,38.38 24.77,38.425 25.059,38.425 25.335,38.701 v4(25.335,38.737)
  Top Layer w0.4: C217.1@24.725,38.32 24.725,38.38 24.725,39.015 25.399,39.69 25.775,39.69 25.959,39.873
  Signal Layer 2 w0.5: v1(35.025,53.925) 59.799,53.925 60.924,52.8 62.107,52.8 63.734,54.428 v1(68.247,54.428)
  Bottom Layer w0.4: v3(62.4,46.325) C195.2@62.4,46.787 ; R35.2@68.661,58.493 R36.2@69.7,58.493 R37.2@70.725,58.493 R34.2@71.75,58.493 ; C89.2@71.75,57.5 R34.2@71.75,58.493 ; R39.2@73.754,58.53 73.717,58.493 R38.2@72.75,58.493 R34.2@71.75,58.493
  Bottom Layer w0.5: v4(25.335,38.737) 25.335,44.91 26.35,45.925 26.35,48.5 25.8,49.05 25.8,51.175 28.55,53.925 v1(35.025,53.925) ; C195.2@62.4,46.787 62.4,47.711 68.247,53.558 v1(68.247,54.428) 68.247,55.608 70.139,57.5 C89.2@71.75,57.5
VLED: C85.2 C93.2 CN2.32 CN2.33 CN2.34 CN2.35 R4.1 | length 3.4
  Top Layer w0.25: CN2.35@5,48.75 5.671,48.75 ; CN2.34@5,49.25 5.671,49.25 ; CN2.33@5,49.75 5.671,49.75 ; CN2.32@5,50.25 5.671,50.25 ; 6.596,49.877 C93.2@6.596,50.549
VREF+: C248.2 C250.2 R269.2 U1.AG6 | length 2.9
  Top Layer w0.09: U1.AG6@58.875,34.825 59.13,34.57
  Top Layer w0.1: 59.13,34.57 59.233,34.467 59.233,34.02
  Top Layer w0.25: R269.2@58.956,32.258 59.051,32.258 59.181,32.388 59.181,32.483 59.233,32.535 C248.2@59.233,33.002 C250.2@59.233,33.572 59.233,34.02
WL.SDMMC3_CK: TP10.1 U1.A26 U40.20 | length 39
  Top Layer w0.1: v1(74.35,69.025) U40.20@75.45,69.025
  Top Layer w0.11: U1.A26@68.875,47.825 68.884,47.834 68.884,48.387 69.706,49.209 69.909,49.209 74.284,53.584 76.409,53.584 76.883,54.058 81.081,54.058 82.184,55.161 82.184,61.891 81.35,62.725 76.639,62.725 75.671,63.693 74.152,63.693 73.754,64.091 TP10.1@73.754,68.471 ; TP10.1@73.754,68.475 73.8,68.475 v1(74.35,69.025)
WL.SDMMC3_CMD: R93.2 U1.B26 U40.22 | length 39.2
  Top Layer w0.09: 68.889,47.485 69.125,47.721 69.125,48.118 69.582,48.575
  Top Layer w0.11: U1.B26@68.875,47.325 68.889,47.339 68.889,47.485 ; 69.582,48.575 69.831,48.824 70.025,48.824 74.476,53.275 76.635,53.275 77.028,53.668 81.34,53.668 82.651,54.979 82.651,62.103 81.549,63.206 76.886,63.206 74.217,65.875 74.217,67.55 74.464,67.797 74.928,67.797 74.95,67.775 75.55,67.775 76.055,68.28 76.055,68.505 U40.22@76.125,68.575 ; R93.2@74.95,67.129 v1(74.95,67.797)
WL.SDMMC3_D0: R92.2 U1.C27 U40.24 | length 38.6
  Top Layer w0.11: U1.C27@69.375,46.825 70.053,47.503 70.109,47.503 70.78,48.173 70.78,48.239 74.9,52.359 77.273,52.359 77.481,52.567 82.226,52.567 84.025,54.366 84.025,63.3 83.097,64.228 82.328,64.228 v1(82.325,64.225) ; R92.2@77.025,67.129 v1(77.025,67.95) U40.24@77.025,68.575
  Bottom Layer w0.11: v1(77.025,67.95) 78.475,67.95 78.85,68.325 80.15,68.325 81.35,67.125 81.35,65.2 v1(82.325,64.225)
WL.SDMMC3_D1: R91.2 U1.D25 U40.26 | length 38.7
  Top Layer w0.09: U1.D25@68.375,46.325 68.402,46.352 68.516,46.352 68.739,46.575 69.553,46.575 70.125,47.147
  Top Layer w0.11: 70.125,47.147 75.028,52.05 77.499,52.05 77.622,52.173 82.567,52.173 84.51,54.116 84.51,63.515 83.199,64.826 v1(80.782,64.826) ; U40.26@77.925,68.575 77.925,68.175 78.122,67.979 78.347,67.979 v1(79.193,67.132)
  Bottom Layer w0.11: v1(79.193,67.132) 79.203,67.142 R91.2@80.045,67.142 80.236,66.952 80.473,66.952 80.782,66.643 v1(80.782,64.826)
WL.SDMMC3_D2: R90.2 U1.C26 U40.23 | length 39.6
  Top Layer w0.09: U1.C26@68.875,46.825 69.125,47.075 69.125,47.429 69.271,47.575 69.487,47.575 69.805,47.893 69.905,47.893 70.125,48.112
  Top Layer w0.11: 70.125,48.112 70.207,48.194 70.207,48.549 74.617,52.959 76.821,52.959 77.174,53.312 81.622,53.312 83.102,54.791 83.102,62.282 82.85,62.533 v1(82.85,63.027) ; R90.2@75.975,67.132 75.975,67.56 v1(76.344,67.929) 76.344,67.984 76.575,68.215 U40.23@76.575,68.575
  Bottom Layer w0.11: v1(76.344,67.929) 77.115,68.7 81.417,68.7 82.85,67.267 v1(82.85,63.027)
WL.SDMMC3_D3: R89.2 U1.B27 U40.25 | length 37.5
  Top Layer w0.11: U1.B27@69.375,47.325 69.398,47.348 69.529,47.348 69.884,47.703 70.012,47.703 70.51,48.2 70.51,48.415 74.748,52.653 77.018,52.653 77.31,52.945 81.918,52.945 83.536,54.563 83.536,63.089 83,63.625 82.1,63.625 v1(81.5,64.225) ; U40.25@77.475,68.575 77.475,68.021 v1(78.164,67.332)
  Bottom Layer w0.11: R89.2@78.164,66.634 v1(78.164,67.332) 77.771,67.332 77.6,67.161 77.6,65.125 78.5,64.225 v1(81.5,64.225)
WL_HOST_WAKE: U1.N2 U40.27 | length 73.7
  Top Layer w0.09: 55.625,41.694 56.153,41.694 56.271,41.575 56.625,41.575 U1.N2@56.875,41.825
  Top Layer w0.1: v2(52.175,41.475) 52.525,41.125 52.849,41.125 53.417,41.694 55.625,41.694
  Top Layer w0.2: U40.27@78.375,68.575 v1(78.375,69.2)
  Signal Layer 2 w0.1: v1(71.35,67.425) 71.401,67.476 71.701,67.476 74.35,70.125 75.059,70.125 76.309,68.875 78.05,68.875 v1(78.375,69.2)
  Signal Layer 3 w0.1: v2(52.175,41.475) 51.675,41.975 51.675,46.064 57.861,52.25 80.45,52.25 82.65,54.45 82.65,57.894 81.346,59.197 78.435,62.109 77.444,63.1 76.375,63.1 73.2,66.275 71.213,66.275 70.925,66.563 70.925,67 v1(71.35,67.425)
WL_REG_ON: TP18.1 U1.L5 U40.28 | length 74.5
  Top Layer w0.09: 55.625,42.494 57.063,42.494 57.144,42.575 58.125,42.575 U1.L5@58.375,42.825
  Top Layer w0.1: v2(52.031,42.8) 52.337,42.494 55.625,42.494
  Top Layer w0.2: U40.28@78.825,68.575 78.836,68.565 78.836,68.157 79.126,67.868 v1(79.193,67.868)
  Signal Layer 2 w0.1: v1(71.35,66.739) 74.536,69.925 74.976,69.925 76.226,68.675 78.386,68.675 v1(79.193,67.868)
  Signal Layer 3 w0.1: v2(52.031,42.8) 52.031,46.137 57.944,52.05 80.533,52.05 82.85,54.367 82.85,57.976 81.346,59.48 78.718,62.109 77.526,63.3 76.458,63.3 73.019,66.739 v1(71.35,66.739)
  Bottom Layer w0.1: TP18.1@51.376,42.803 52.028,42.803 v2(52.031,42.8)
pads on no net: CART-1.1 CN1.14 CN2.20 CN2.21 CN2.22 CN2.23 CN2.24 CN2.25 CN2.26 CN2.27 CN2.28 CN2.29 CN6.NPTH1 CN6.NPTH2 CN15.0 CN15.A8 CN15.B8 CN16.17 CN16.18 CN21.0 CN21.A2 CN21.A3 CN21.A8 CN21.A10 CN21.A11 CN21.B2 CN21.B3 CN21.B8 CN21.B10 CN21.B11 D1.2 L9.2 MIRE1.1 MIRE2.1 MIRE3.1 MIRE4.1 MIRE5.1 MIRE6.1 U1.A15 U1.A18 U1.AA7 U1.AA21 U1.AA23 U1.AB10 U1.AB24 U1.AC7 U1.AC23 U1.AC25 U1.AD20 U1.AD25 U1.AE7 U1.AE8 U1.AE9 U1.AE10 U1.AE25 U1.AE26 U1.AF7 U1.AF26 U1.AG9 U1.AG26 U1.B1 U1.B2 U1.B18 U1.C2 U1.C3 U1.C15 U1.C16 U1.C17 U1.C18 U1.D3 U1.D16 U1.D20 U1.E1 U1.E2 U1.E3 U1.F1 U1.F2 U1.G21 U1.K24 U1.L21 U1.N3 U1.U1 U1.W21 U1.W23 U1.Y22 U2.A1 U2.A2 U2.A8 U2.A11 U2.A12 U2.AA1 U2.AA12 U2.AB1 U2.AB2 U2.AB11 U2.AB12 U2.B1 U2.B12 U2.G11 U2.H3 U2.J5 U2.K5 U2.K8 U2.N5 U2.N8 U2.P5 U2.R3 U5.5 U5.6 U6.5 U6.6 U34.6 U35.4 U36.A1 U36.A3 U36.A4 U36.A5 U36.A8 U36.A9 U36.A11 U36.A12 U36.A13 U36.B4 U36.B5 U36.B6 U36.B7 U36.B8 U36.B9 U36.B10 U36.B11 U36.B12 U36.B13 U36.B15 U36.C2 U36.C3 U36.C12 U36.C13 U36.C14 U36.C15 U36.D1 U36.D2 U36.D3 U36.D11 U36.D13 U36.D14 U36.E1 U36.E2 U36.E3 U36.E4 U36.E12 U36.E13 U36.E14 U36.E15 U36.F1 U36.F4 U36.F14 U36.G4 U36.G14 U36.G15 U36.H2 U36.H3 U36.H4 U36.H14 U36.J3 U36.J4 U36.K1 U36.K2 U36.K3 U36.K12 U36.K13 U36.K14 U36.K15 U36.L1 U36.L12 U36.L13 U36.L14 U36.L15 U36.M2 U36.M3 U36.M4 U36.M7 U36.M12 U36.M13 U36.M14 U36.M15 U36.N2 U36.N4 U36.N6 U36.N7 U36.N11 U36.N13 U36.N14 U36.N15 U36.P2 U36.P4 U36.P5 U36.P6 U36.P7 U36.P8 U36.P9 U36.P10 U36.P11 U36.P12 U36.P13 U36.P14 U36.P15 U36.R2 U36.R3 U36.R6 U36.R7 U36.R8 U36.R9 U36.R10 U36.R11 U36.R12 U37.A1 U37.A2 U37.A7 U37.A8 U37.A9 U37.A10 U37.A11 U37.A12 U37.A13 U37.A14 U37.B1 U37.B7 U37.B8 U37.B9 U37.B10 U37.B11 U37.B12 U37.B13 U37.B14 U37.C1 U37.C3 U37.C5 U37.C7 U37.C8 U37.C9 U37.C10 U37.C11 U37.C12 U37.C13 U37.C14 U37.D1 U37.D2 U37.D3 U37.D4 U37.D12 U37.D13 U37.D14 U37.E1 U37.E2 U37.E3 U37.E5 U37.E8 U37.E9 U37.E10 U37.E12 U37.E13 U37.E14 U37.F1 U37.F2 U37.F3 U37.F10 U37.F12 U37.F13 U37.F14 U37.G1 U37.G2 U37.G3 U37.G10 U37.G12 U37.G13 U37.G14 U37.H1 U37.H2 U37.H3 U37.H12 U37.H13 U37.H14 U37.J1 U37.J2 U37.J3 U37.J12 U37.J13 U37.J14 U37.K1 U37.K2 U37.K3 U37.K6 U37.K7 U37.K10 U37.K12 U37.K13 U37.K14 U37.L1 U37.L2 U37.L3 U37.L12 U37.L13 U37.L14 U37.M1 U37.M2 U37.M3 U37.M7 U37.M8 U37.M9 U37.M10 U37.M11 U37.M12 U37.M13 U37.M14 U37.N1 U37.N3 U37.N6 U37.N7 U37.N8 U37.N9 U37.N10 U37.N11 U37.N12 U37.N13 U37.N14 U37.P1 U37.P2 U37.P7 U37.P8 U37.P9 U37.P10 U37.P11 U37.P12 U37.P13 U37.P14 U40.6 U40.7 U40.13 U40.15 U40.16 U50.7 U50.8

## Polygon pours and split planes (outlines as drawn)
GND on Signal Layer 4 "GND_L05_P040" (solid, remove dead copper, pour order 40): 0,79.6 100,79.6 100,0 0,0
VDD2_DDR on Signal Layer 4 "VDDDDR" (solid, remove dead copper, pour order 5): 64.931,42.886 64.931,44.139 66.087,45.295 66.087,46.319 66.087,48.281 63.827,50.54 62.267,52.1 18.046,52.1 17.726,51.78 17.726,46.476 16.723,45.473 15.425,45.473 14.754,46.144 14.754,53.383 19.361,57.99 60.436,57.99 78.392,57.99 90.539,45.925 90.539,33.475 70.6,33.475 70.556,33.525 64.931,39.15
3V3 on Signal Layer 4 "3V3_L4" (solid, remove dead copper, pour order 29): 92.682,7.266 88.115,7.266 86.232,5.382 81.027,5.382 70.119,16.29 39.454,16.29 26.362,29.382 6.407,29.382 4.135,27.11 4.135,8.51 3.55,7.925 1.725,7.925 1.429,8.221 1.429,33.104 4.135,35.81 4.135,65.75 10.773,72.388 83.787,72.388 89.13,67.045 89.13,56.558 87.538,56.558 82.459,61.637 55.077,61.637 51.495,65.24 45.565,65.24 41.962,61.637 22.498,61.637 12.86,51.999 12.86,41.538 13.871,40.527 30.8,40.527 40.125,31.202 40.125,30.192 45.13,25.187 86.604,25.187 92.182,30.765 97.985,30.765 98.575,30.175 98.575,7.257
VDDCORE on Signal Layer 4 "VDDCORE" (solid, remove dead copper, pour order 1): 61.625,43.6 61.625,45.05 60.125,46.55 42.252,46.55 42.252,41.475 62.35,41.475 62.35,42.825
VDDGPU on Signal Layer 4 "VDDGPU" (solid, remove dead copper, pour order 4): 60.186,41.55 60.186,41.222 62.375,39.033 62.375,38.541 61.767,37.933 60.108,37.933 57.875,35.725 42.875,35.725 41.05,37.55 41.05,39.792 42.131,40.873 42.131,45.3 36.631,45.3 35.1,43.769 35.1,39.961 36.42,38.673 36.42,34.94 46.156,25.4 62.956,25.4 67.975,30.419 67.975,36.006 65.425,38.556 65.425,41.55
VBUS_STLK on Signal Layer 4 "VBUS_STLK_L4" (solid, remove dead copper, pour order 31): 6.28,21.818 8.611,24.149 10.519,24.149 13.49,21.178 13.49,17.925 19.715,11.7 27.05,11.7 27.73,11.02 27.73,7.516 24.304,4.09 14.349,4.09 6.28,12.159
VDDIO on Signal Layer 4 "VDDIO" (solid, remove dead copper, pour order 3): 62.35,38.55 61.732,37.933 60.083,37.933 57.875,35.725 42.875,35.725 41.05,37.55 41.05,39.807 42.693,41.45 48.962,41.45 59.979,41.45 62.35,39.08
VDDCPU on Signal Layer 4 "VDDCPU" (solid, remove dead copper, pour order 2): 65.325,44.003 66.023,44.701 66.023,48.344 62.267,52.1 44.625,52.1 18.046,52.1 17.726,51.78 17.726,49.414 20.59,46.55 60.125,46.55 61.138,45.537 61.138,44.65 61.138,41.575 65.325,41.575
GND on Top Layer "GND_L01_P037" (solid, remove dead copper, pour order 37): -0.051,79.556 99.949,79.556 99.948,-0.044 -0.051,-0.044
VBUSc on Top Layer "VBUSc" (solid, remove dead copper, pour order 26): 89.113,7.784 87.1,7.784 87.1,13.417 91.525,17.842 91.525,20.18 93.46,20.18 93.46,15.437 89.113,11.09
VDDIO on Top Layer "VDDIO" (solid, pour order 22): 30.995,46.77 30.995,48.568 31.53,49.103 31.712,49.103 32.15,48.664 32.15,48.123 31.45,47.423 31.45,46.77
VDDCORE on Top Layer "I_SENS_VDDCORE_P" (solid, pour order 19): 41.007,52.695 43.889,49.813 43.889,43.586 43.894,43.581 42.44,43.581 41.895,44.126 41.895,48.827 41.522,49.2 39.875,49.2 35.515,49.2 35.505,52.695
VLED on Top Layer "VLED" (solid, remove dead copper, pour order 14): 5.45,48.625 8.139,48.625 8.139,52.099 7.289,52.099 7.289,50.959 7.134,50.804 6.316,50.804 5.887,50.375 5.45,50.375
5V_STLK on Top Layer "5V_VIN" (solid, pour order 17): 22.51,43.62 23.167,43.62 23.35,43.803 23.35,43.463 22.867,42.98 22.51,42.98
VDDCPU on Top Layer "I_SENS_VDDCPU_P" (solid, pour order 18): 17.812,51.845 17.812,49.998 18.335,49.475 22.75,49.475 22.745,49.48 22.745,51.845
VDDGPU on Top Layer "I_SENS_VDDGPU_P" (solid, pour order 20): 41.603,43.6 41.745,43.742 41.745,46.72 37.025,46.72 37.025,43.6
3V3 on Top Layer "3V3" (solid, pour order 23): 12.887,36.548 13.062,36.373 19.41,36.373 20.712,37.675 20.712,38.523 13.088,38.523 12.887,38.323
NetL6_1 on Top Layer "NetL13_1" (solid, pour order 25): 33.375,41.863 33.838,41.4 35.1,41.4 35.1,39.1 35.098,39.098 33.801,39.098 33.801,40.722 33.375,41.148
GND on Bottom Layer "GND_L06_P042" (solid, remove dead copper, pour order 42): -0.072,79.484 99.928,79.484 99.928,-0.116 -0.072,-0.116
VBAT on Bottom Layer "VBAT_L6" (solid, remove dead copper, pour order 24): 59.164,39.13 58.308,38.274 57.351,38.274 56.254,39.371 56.245,39.371 56.699,39.825 57.875,39.825 58.24,40.19 58.937,40.19 59.164,39.964
GND on Signal Layer 3 "GND_L04_P036" (solid, remove dead copper, pour order 36): 0,79.6 100,79.6 100,0 0,0
1V8 on Signal Layer 3 "1V8_L3" (solid, remove dead copper, pour order 34): 60.334,68.688 69.966,59.055 79.858,59.055 81.735,57.179 81.735,55.984 79.917,54.167 63.687,54.167 57.984,59.87 39.42,59.87 31.674,52.124 28.876,52.124 28.526,52.474 28.526,53.397 33.061,57.931 33.061,63.752 37.996,68.688
3V3_STLK on Signal Layer 3 "3V3_STLK_L3" (solid, remove dead copper, pour order 28): 28.711,31.18 28.144,31.18 26.486,29.522 21.759,29.522 18.85,32.431 18.85,33.795 15.926,33.795 15.926,15.814 17.29,14.45 24.475,14.45 27.807,11.118 29.725,9.2 30.052,9.2 31.628,10.776 31.628,15.905 29.568,17.965 29.568,30.324
VBUSc on Signal Layer 3 "VBUSc_L3" (solid, remove dead copper, pour order 33): 89.022,10.449 83.057,10.449 81.687,9.079 81.687,7.387 82.075,7 88.227,7 89.022,7.795
3V3_DVDD_RGMII on Signal Layer 3 "3V3_DVDD_RGMII_L3" (solid, remove dead copper, pour order 27): 40.225,24.385 40.225,31.194 39.25,32.264 39.25,34.58 44.006,34.58 44.675,33.911 44.675,32.69 49.265,28.1 49.265,25.473 47.415,23.622 40.944,23.666
VDDIO on Signal Layer 3 "VDDIO_L3" (solid, remove dead copper, pour order 32): 60.326,37.901 62.326,37.901 63.625,39.2 63.625,45.6 62.9,46.325 60.364,46.325 59.931,45.892 59.931,40.206 59.725,40 59.725,38.475
GND on Signal Layer 2 "GND_L03_P041" (solid, remove dead copper, pour order 41): 0,79.6 100,79.6 100,0 0,0
1V8 on Signal Layer 2 "1V8_L2" (solid, remove dead copper, pour order 38): 67.971,37.43 66.1,39.302 66.1,45.145 64.484,46.76 63.818,47.427 46.015,47.427 42.92,50.521 33.947,50.521 30.845,53.623 28.785,53.623 28.423,53.261 28.423,52.185 29.383,51.225 29.763,51.225 31.665,49.323 35.227,49.323 39.176,45.374 47.231,45.374 55.607,36.999 55.607,34.227 56.104,33.73 57.271,33.73 57.271,31.029 58.106,30.195 59.82,30.195 62.375,32.75 62.375,35.1 63.1,35.825 67.552,35.825 67.971,36.245
VDD1_DDR on Signal Layer 2 "VDD1_DDR_L2" (solid, remove dead copper, pour order 30): 28.939,55.425 28.642,55.128 24.056,55.128 18.85,49.922 18.85,45.081 19.131,44.8 20.061,44.8 20.385,45.124 20.385,46.985 27.223,53.823 30.827,53.823 33.9,50.75 42.691,50.75 46.015,47.427 71.721,47.427 81.198,37.95 90.033,37.95 90.834,38.751 90.834,46.566 84.667,52.733 61.088,52.733 59.896,53.925 35.025,53.925 33.525,55.425
5V_STLK on Signal Layer 2 "5V_STLK_L2" (solid, remove dead copper, pour order 35): 36.075,38.323 34.569,36.817 27.867,36.817 27.027,35.977 27.027,33.924 26.373,33.257 22.575,33.257 17.94,28.622 17.94,18.457 24.16,12.237 71.353,12.237 82.38,23.264 85,23.264 86.773,23.264 89.393,20.645 89.393,15.195 91.562,13.025 96.331,13.025 97.27,12.086 97.27,6.345 93.725,2.8 12.29,2.8 5.9,9.19 5.9,59.764 21.92,75.784 49.079,75.784 49.079,74.404 47.064,72.388 22.975,72.388 9,58.413 9,54 18.2,44.8 20.061,44.8 20.385,45.124 20.385,46.985 23.625,50.225 27.75,50.225 28.652,49.323 35.227,49.323 36.075,48.475
GND on Signal Layer 1 "GND_L02_P000" (solid, remove dead copper, pour order 0): 0,79.6 100,79.6 100,0 0,0

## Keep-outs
Bottom Layer:
  circle w3.7: c94.73,41.89 r1.84
  circle w3.7: c14.25,49.625 r1.84
  circle w4: c13.965,9.211 r2
  circle w4: c42.326,73.3 r2
  circle w4: c56.826,73.3 r2
  circle w3.7: c14.25,50.875 r1.84
  circle w4: c22.575,33.257 r2
  circle w4: c20.035,33.257 r2
  circle w4: c25.115,33.257 r2
  circle w4: c17.495,33.257 r2
  circle w4: c16.505,9.211 r2
  circle w4.3: c33.75,10.45 r2.15
  circle w4.9: c59.93,13.48 r2.483
  circle w4.9: c73.07,13.48 r2.483
  circle w3.7: c94.73,16.49 r1.84
  circle w3.7: c94.73,19.03 r1.84
  circle w3.7: c40.865,16.29 r1.84
  circle w3.7: c35.785,16.29 r1.84
  circle w3.7: c45.945,16.29 r1.84
Keep-Out Layer:
  region: 90.115,66.003 90.115,58.875 100,58.875 100,66.003
  rectangle: 90.115,65.6 91.675,79.6
  lines w0.1: 1.25,70.259 1.25,72.409 10.15,72.409 10.15,70.259 1.25,70.259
